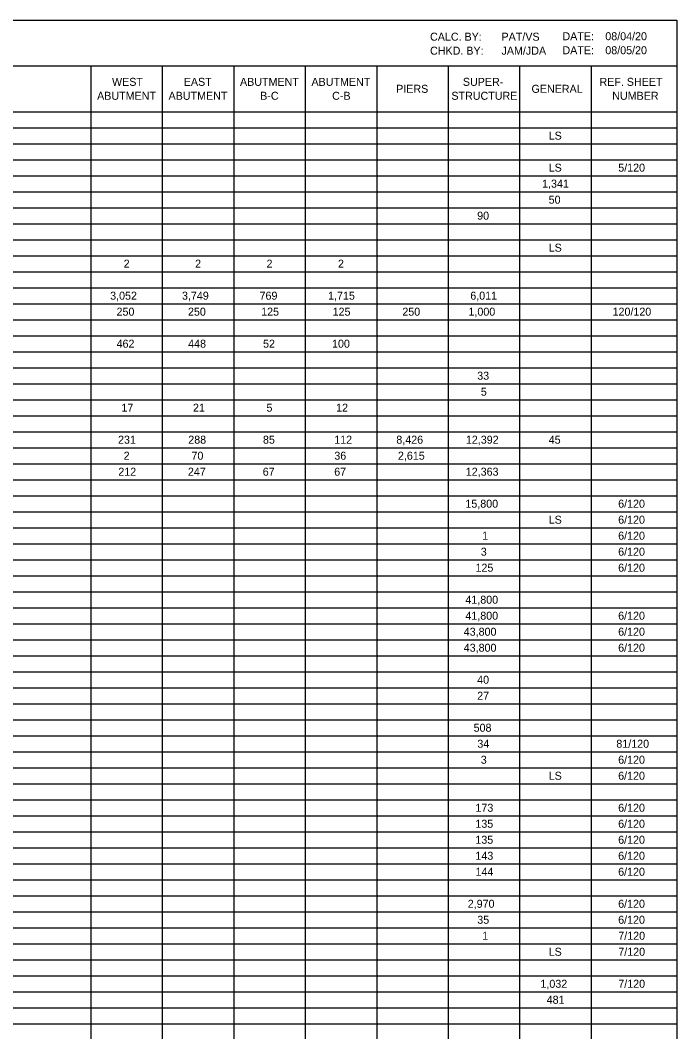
# Model space of a CAD drawing. Extents: x 100 to 128, y 64.8 to 100.
# Drawn here: x 116.51 to 128, y 82.3 to 100 of the extents above; entities that cross this region are included whole.
import ezdxf

# ---------------------------------------------------------------- set-up
doc = ezdxf.new("R2010")
doc.units = 0
doc.layers.add('SH_Text', color=7, linetype='Continuous')

msp = doc.modelspace()

# ---------------------------------------------------------------- linework, layer by layer
at = {"layer": 'SH_Text'}
for p, q in [((100, 100), (128, 100)), ((128, 100), (128, 98.4)), ((100, 99.2), (128, 99.2)), ((117.75, 99.2), (117.75, 98.4)), ((119, 99.2), (119, 98.4)), ((120.25, 99.2), (120.25, 98.4)), ((121.5, 99.2), (121.5, 98.4)), ((122.75, 99.2), (122.75, 98.4)), ((124, 99.2), (124, 98.4)), ((125.25, 99.2), (125.25, 98.4)), ((126.5, 99.2), (126.5, 98.4)), ((100, 98.4), (128, 98.4)), ((100, 98.4), (128, 98.4)), ((117.75, 98.4), (117.75, 95.32)), ((119, 98.4), (119, 95.32)), ((120.25, 98.4), (120.25, 95.32)), ((121.5, 98.4), (121.5, 95.32)), ((122.75, 98.4), (122.75, 95.32)), ((124, 98.4), (124, 95.32)), ((125.25, 98.4), (125.25, 95.32)), ((126.5, 98.4), (126.5, 95.32)), ((128, 98.4), (128, 95.32)), ((100, 98.12), (128, 98.12)), ((100, 97.84), (128, 97.84)), ((100, 97.56), (128, 97.56)), ((100, 97.28), (128, 97.28)), ((100, 97), (128, 97)), ((100, 96.72), (128, 96.72)), ((100, 96.44), (128, 96.44)), ((100, 96.16), (128, 96.16)), ((100, 95.88), (128, 95.88)), ((100, 95.6), (128, 95.6)), ((100, 95.32), (128, 95.32)), ((117.75, 95.32), (117.75, 92.24)), ((119, 95.32), (119, 92.24)), ((120.25, 95.32), (120.25, 92.24)), ((121.5, 95.32), (121.5, 92.24)), ((122.75, 95.32), (122.75, 92.24)), ((124, 95.32), (124, 92.24)), ((125.25, 95.32), (125.25, 92.24)), ((126.5, 95.32), (126.5, 92.24)), ((128, 95.32), (128, 92.24)), ((100, 95.04), (128, 95.04)), ((100, 94.76), (128, 94.76)), ((100, 94.48), (128, 94.48)), ((100, 94.2), (128, 94.2)), ((100, 93.92), (128, 93.92)), ((100, 93.64), (128, 93.64)), ((100, 93.36), (128, 93.36)), ((100, 93.08), (128, 93.08)), ((100, 92.8), (128, 92.8)), ((100, 92.52), (128, 92.52)), ((100, 92.24), (128, 92.24)), ((117.75, 92.24), (117.75, 91.96)), ((119, 92.24), (119, 91.96)), ((120.25, 92.24), (120.25, 91.96)), ((121.5, 92.24), (121.5, 91.96)), ((122.75, 92.24), (122.75, 91.96)), ((124, 92.24), (124, 91.96)), ((125.25, 92.24), (125.25, 91.96)), ((126.5, 92.24), (126.5, 91.96)), ((128, 92.24), (128, 91.96)), ((100, 91.96), (128, 91.96)), ((117.75, 91.96), (117.75, 91.68)), ((119, 91.96), (119, 91.68)), ((120.25, 91.96), (120.25, 91.68)), ((121.5, 91.96), (121.5, 91.68)), ((122.75, 91.96), (122.75, 91.68)), ((124, 91.96), (124, 91.68)), ((125.25, 91.96), (125.25, 91.68)), ((126.5, 91.96), (126.5, 91.68)), ((128, 91.96), (128, 91.68)), ((100, 91.68), (128, 91.68)), ((117.75, 91.68), (117.75, 91.4)), ((119, 91.68), (119, 91.4)), ((120.25, 91.68), (120.25, 91.4)), ((121.5, 91.68), (121.5, 91.4)), ((122.75, 91.68), (122.75, 91.4)), ((124, 91.68), (124, 91.4)), ((125.25, 91.68), (125.25, 91.4)), ((126.5, 91.68), (126.5, 91.4)), ((128, 91.68), (128, 91.4)), ((100, 91.4), (128, 91.4)), ((117.75, 91.4), (117.75, 91.12)), ((119, 91.4), (119, 91.12)), ((120.25, 91.4), (120.25, 91.12)), ((121.5, 91.4), (121.5, 91.12)), ((122.75, 91.4), (122.75, 91.12)), ((124, 91.4), (124, 91.12)), ((125.25, 91.4), (125.25, 91.12)), ((126.5, 91.4), (126.5, 91.12)), ((128, 91.4), (128, 91.12)), ((100, 91.12), (128, 91.12)), ((117.75, 91.12), (117.75, 90.84)), ((119, 91.12), (119, 90.84)), ((120.25, 91.12), (120.25, 90.84)), ((121.5, 91.12), (121.5, 90.84)), ((122.75, 91.12), (122.75, 90.84)), ((124, 91.12), (124, 90.84)), ((125.25, 91.12), (125.25, 90.84)), ((126.5, 91.12), (126.5, 90.84)), ((128, 91.12), (128, 90.84)), ((100, 90.84), (128, 90.84)), ((117.75, 90.84), (117.75, 90.56)), ((119, 90.84), (119, 90.56)), ((120.25, 90.84), (120.25, 90.56)), ((121.5, 90.84), (121.5, 90.56)), ((122.75, 90.84), (122.75, 90.56)), ((124, 90.84), (124, 90.56)), ((125.25, 90.84), (125.25, 90.56)), ((126.5, 90.84), (126.5, 90.56)), ((128, 90.84), (128, 90.56)), ((100, 90.56), (128, 90.56)), ((117.75, 90.56), (117.75, 90.28)), ((119, 90.56), (119, 90.28)), ((120.25, 90.56), (120.25, 90.28)), ((121.5, 90.56), (121.5, 90.28)), ((122.75, 90.56), (122.75, 90.28)), ((124, 90.56), (124, 90.28)), ((125.25, 90.56), (125.25, 90.28)), ((126.5, 90.56), (126.5, 90.28)), ((128, 90.56), (128, 90.28)), ((100, 90.28), (128, 90.28)), ((117.75, 90.28), (117.75, 90)), ((119, 90.28), (119, 90)), ((120.25, 90.28), (120.25, 90)), ((121.5, 90.28), (121.5, 90)), ((122.75, 90.28), (122.75, 90)), ((124, 90.28), (124, 90)), ((125.25, 90.28), (125.25, 90)), ((126.5, 90.28), (126.5, 90)), ((128, 90.28), (128, 90)), ((100, 90), (128, 90)), ((117.75, 90), (117.75, 89.72)), ((119, 90), (119, 89.72)), ((120.25, 90), (120.25, 89.72)), ((121.5, 90), (121.5, 89.72)), ((122.75, 90), (122.75, 89.72)), ((124, 90), (124, 89.72)), ((125.25, 90), (125.25, 89.72)), ((126.5, 90), (126.5, 89.72)), ((128, 90), (128, 89.72)), ((100, 89.72), (128, 89.72)), ((117.75, 89.72), (117.75, 89.44)), ((119, 89.72), (119, 89.44)), ((120.25, 89.72), (120.25, 89.44)), ((121.5, 89.72), (121.5, 89.44)), ((122.75, 89.72), (122.75, 89.44)), ((124, 89.72), (124, 89.44)), ((125.25, 89.72), (125.25, 89.44)), ((126.5, 89.72), (126.5, 89.44)), ((128, 89.72), (128, 89.44)), ((100, 89.44), (128, 89.44)), ((117.75, 89.44), (117.75, 89.16)), ((119, 89.44), (119, 89.16)), ((120.25, 89.44), (120.25, 89.16)), ((121.5, 89.44), (121.5, 89.16)), ((122.75, 89.44), (122.75, 89.16)), ((124, 89.44), (124, 89.16)), ((125.25, 89.44), (125.25, 89.16)), ((126.5, 89.44), (126.5, 89.16)), ((128, 89.44), (128, 89.16)), ((100, 89.16), (128, 89.16)), ((117.75, 89.16), (117.75, 88.88)), ((119, 89.16), (119, 88.88)), ((120.25, 89.16), (120.25, 88.88)), ((121.5, 89.16), (121.5, 88.88)), ((122.75, 89.16), (122.75, 88.88)), ((124, 89.16), (124, 88.88)), ((125.25, 89.16), (125.25, 88.88)), ((126.5, 89.16), (126.5, 88.88)), ((128, 89.16), (128, 88.88)), ((100, 88.88), (128, 88.88)), ((117.75, 88.88), (117.75, 88.6)), ((119, 88.88), (119, 88.6)), ((120.25, 88.88), (120.25, 88.6)), ((121.5, 88.88), (121.5, 88.6)), ((122.75, 88.88), (122.75, 88.6)), ((124, 88.88), (124, 88.6)), ((125.25, 88.88), (125.25, 88.6)), ((126.5, 88.88), (126.5, 88.6)), ((128, 88.88), (128, 88.6)), ((100, 88.6), (128, 88.6)), ((117.75, 88.6), (117.75, 88.32)), ((119, 88.6), (119, 88.32)), ((120.25, 88.6), (120.25, 88.32)), ((121.5, 88.6), (121.5, 88.32)), ((122.75, 88.6), (122.75, 88.32)), ((124, 88.6), (124, 88.32)), ((125.25, 88.6), (125.25, 88.32)), ((126.5, 88.6), (126.5, 88.32)), ((128, 88.6), (128, 88.32)), ((100, 88.32), (128, 88.32)), ((117.75, 88.32), (117.75, 88.04)), ((119, 88.32), (119, 88.04)), ((120.25, 88.32), (120.25, 88.04)), ((121.5, 88.32), (121.5, 88.04)), ((122.75, 88.32), (122.75, 88.04)), ((124, 88.32), (124, 88.04)), ((125.25, 88.32), (125.25, 88.04)), ((126.5, 88.32), (126.5, 88.04)), ((128, 88.32), (128, 88.04)), ((100, 88.04), (128, 88.04)), ((117.75, 88.04), (117.75, 87.76)), ((119, 88.04), (119, 87.76)), ((120.25, 88.04), (120.25, 87.76)), ((121.5, 88.04), (121.5, 87.76)), ((122.75, 88.04), (122.75, 87.76)), ((124, 88.04), (124, 87.76)), ((125.25, 88.04), (125.25, 87.76)), ((126.5, 88.04), (126.5, 87.76)), ((128, 88.04), (128, 87.76)), ((100, 87.76), (128, 87.76)), ((117.75, 87.76), (117.75, 87.48)), ((119, 87.76), (119, 87.48)), ((120.25, 87.76), (120.25, 87.48)), ((121.5, 87.76), (121.5, 87.48)), ((122.75, 87.76), (122.75, 87.48)), ((124, 87.76), (124, 87.48)), ((125.25, 87.76), (125.25, 87.48)), ((126.5, 87.76), (126.5, 87.48)), ((128, 87.76), (128, 87.48)), ((100, 87.48), (128, 87.48)), ((117.75, 87.48), (117.75, 87.2)), ((119, 87.48), (119, 87.2)), ((120.25, 87.48), (120.25, 87.2)), ((121.5, 87.48), (121.5, 87.2)), ((122.75, 87.48), (122.75, 87.2)), ((124, 87.48), (124, 87.2)), ((125.25, 87.48), (125.25, 87.2)), ((126.5, 87.48), (126.5, 87.2)), ((128, 87.48), (128, 87.2)), ((100, 87.2), (128, 87.2)), ((117.75, 87.2), (117.75, 86.92)), ((119, 87.2), (119, 86.92)), ((120.25, 87.2), (120.25, 86.92)), ((121.5, 87.2), (121.5, 86.92)), ((122.75, 87.2), (122.75, 86.92)), ((124, 87.2), (124, 86.92)), ((125.25, 87.2), (125.25, 86.92)), ((126.5, 87.2), (126.5, 86.92)), ((128, 87.2), (128, 86.92)), ((100, 86.92), (128, 86.92)), ((117.75, 86.92), (117.75, 86.64)), ((119, 86.92), (119, 86.64)), ((120.25, 86.92), (120.25, 86.64)), ((121.5, 86.92), (121.5, 86.64)), ((122.75, 86.92), (122.75, 86.64)), ((124, 86.92), (124, 86.64)), ((125.25, 86.92), (125.25, 86.64)), ((126.5, 86.92), (126.5, 86.64)), ((128, 86.92), (128, 86.64)), ((100, 86.64), (128, 86.64)), ((117.75, 86.64), (117.75, 86.36)), ((119, 86.64), (119, 86.36)), ((120.25, 86.64), (120.25, 86.36)), ((121.5, 86.64), (121.5, 86.36)), ((122.75, 86.64), (122.75, 86.36)), ((124, 86.64), (124, 86.36)), ((125.25, 86.64), (125.25, 86.36)), ((126.5, 86.64), (126.5, 86.36)), ((128, 86.64), (128, 86.36)), ((100, 86.36), (128, 86.36)), ((117.75, 86.36), (117.75, 86.08)), ((119, 86.36), (119, 86.08)), ((120.25, 86.36), (120.25, 86.08)), ((121.5, 86.36), (121.5, 86.08)), ((122.75, 86.36), (122.75, 86.08)), ((124, 86.36), (124, 86.08)), ((125.25, 86.36), (125.25, 86.08)), ((126.5, 86.36), (126.5, 86.08)), ((128, 86.36), (128, 86.08)), ((100, 86.08), (128, 86.08)), ((117.75, 86.08), (117.75, 85.8)), ((119, 86.08), (119, 85.8)), ((120.25, 86.08), (120.25, 85.8)), ((121.5, 86.08), (121.5, 85.8)), ((122.75, 86.08), (122.75, 85.8)), ((124, 86.08), (124, 85.8)), ((125.25, 86.08), (125.25, 85.8)), ((126.5, 86.08), (126.5, 85.8)), ((128, 86.08), (128, 85.8)), ((100, 85.8), (128, 85.8)), ((117.75, 85.8), (117.75, 85.52)), ((119, 85.8), (119, 85.52)), ((120.25, 85.8), (120.25, 85.52)), ((121.5, 85.8), (121.5, 85.52)), ((122.75, 85.8), (122.75, 85.52)), ((124, 85.8), (124, 85.52)), ((125.25, 85.8), (125.25, 85.52)), ((126.5, 85.8), (126.5, 85.52)), ((128, 85.8), (128, 85.52)), ((100, 85.52), (128, 85.52)), ((117.75, 85.52), (117.75, 85.24)), ((119, 85.52), (119, 85.24)), ((120.25, 85.52), (120.25, 85.24)), ((121.5, 85.52), (121.5, 85.24)), ((122.75, 85.52), (122.75, 85.24)), ((124, 85.52), (124, 85.24)), ((125.25, 85.52), (125.25, 85.24)), ((126.5, 85.52), (126.5, 85.24)), ((128, 85.52), (128, 85.24)), ((100, 85.24), (128, 85.24)), ((117.75, 85.24), (117.75, 84.96)), ((119, 85.24), (119, 84.96)), ((120.25, 85.24), (120.25, 84.96)), ((121.5, 85.24), (121.5, 84.96)), ((122.75, 85.24), (122.75, 84.96)), ((124, 85.24), (124, 84.96)), ((125.25, 85.24), (125.25, 84.96)), ((126.5, 85.24), (126.5, 84.96)), ((128, 85.24), (128, 84.96)), ((100, 84.96), (128, 84.96)), ((117.75, 84.96), (117.75, 84.68)), ((119, 84.96), (119, 84.68)), ((120.25, 84.96), (120.25, 84.68)), ((121.5, 84.96), (121.5, 84.68)), ((122.75, 84.96), (122.75, 84.68)), ((124, 84.96), (124, 84.68)), ((125.25, 84.96), (125.25, 84.68)), ((126.5, 84.96), (126.5, 84.68)), ((128, 84.96), (128, 84.68)), ((100, 84.68), (128, 84.68)), ((117.75, 84.68), (117.75, 84.4)), ((119, 84.68), (119, 84.4)), ((120.25, 84.68), (120.25, 84.4)), ((121.5, 84.68), (121.5, 84.4)), ((122.75, 84.68), (122.75, 84.4)), ((124, 84.68), (124, 84.4)), ((125.25, 84.68), (125.25, 84.4)), ((126.5, 84.68), (126.5, 84.4)), ((128, 84.68), (128, 84.4)), ((100, 84.4), (128, 84.4)), ((117.75, 84.4), (117.75, 84.12)), ((119, 84.4), (119, 84.12)), ((120.25, 84.4), (120.25, 84.12)), ((121.5, 84.4), (121.5, 84.12)), ((122.75, 84.4), (122.75, 84.12)), ((124, 84.4), (124, 84.12)), ((125.25, 84.4), (125.25, 84.12)), ((126.5, 84.4), (126.5, 84.12)), ((128, 84.4), (128, 84.12)), ((100, 84.12), (128, 84.12)), ((117.75, 84.12), (117.75, 83.84)), ((119, 84.12), (119, 83.84)), ((120.25, 84.12), (120.25, 83.84)), ((121.5, 84.12), (121.5, 83.84)), ((122.75, 84.12), (122.75, 83.84)), ((124, 84.12), (124, 83.84)), ((125.25, 84.12), (125.25, 83.84)), ((126.5, 84.12), (126.5, 83.84)), ((128, 84.12), (128, 83.84)), ((100, 83.84), (128, 83.84)), ((117.75, 83.84), (117.75, 83.56)), ((119, 83.84), (119, 83.56)), ((120.25, 83.84), (120.25, 83.56)), ((121.5, 83.84), (121.5, 83.56)), ((122.75, 83.84), (122.75, 83.56)), ((124, 83.84), (124, 83.56)), ((125.25, 83.84), (125.25, 83.56)), ((126.5, 83.84), (126.5, 83.56)), ((128, 83.84), (128, 83.56)), ((100, 83.56), (128, 83.56)), ((117.75, 83.56), (117.75, 83.28)), ((119, 83.56), (119, 83.28)), ((120.25, 83.56), (120.25, 83.28)), ((121.5, 83.56), (121.5, 83.28)), ((122.75, 83.56), (122.75, 83.28)), ((124, 83.56), (124, 83.28)), ((125.25, 83.56), (125.25, 83.28)), ((126.5, 83.56), (126.5, 83.28)), ((128, 83.56), (128, 83.28)), ((100, 83.28), (128, 83.28)), ((117.75, 83.28), (117.75, 83)), ((119, 83.28), (119, 83)), ((120.25, 83.28), (120.25, 83)), ((121.5, 83.28), (121.5, 83)), ((122.75, 83.28), (122.75, 83)), ((124, 83.28), (124, 83)), ((125.25, 83.28), (125.25, 83)), ((126.5, 83.28), (126.5, 83)), ((128, 83.28), (128, 83)), ((100, 83), (128, 83)), ((117.75, 83), (117.75, 82.72)), ((119, 83), (119, 82.72)), ((120.25, 83), (120.25, 82.72)), ((121.5, 83), (121.5, 82.72)), ((122.75, 83), (122.75, 82.72)), ((124, 83), (124, 82.72)), ((125.25, 83), (125.25, 82.72)), ((126.5, 83), (126.5, 82.72)), ((128, 83), (128, 82.72)), ((100, 82.72), (128, 82.72)), ((117.75, 82.72), (117.75, 82.44)), ((119, 82.72), (119, 82.44)), ((120.25, 82.72), (120.25, 82.44)), ((121.5, 82.72), (121.5, 82.44)), ((122.75, 82.72), (122.75, 82.44)), ((124, 82.72), (124, 82.44)), ((125.25, 82.72), (125.25, 82.44)), ((126.5, 82.72), (126.5, 82.44)), ((128, 82.72), (128, 82.44)), ((100, 82.44), (128, 82.44)), ((117.75, 82.44), (117.75, 82.16)), ((119, 82.44), (119, 82.16)), ((120.25, 82.44), (120.25, 82.16)), ((121.5, 82.44), (121.5, 82.16)), ((122.75, 82.44), (122.75, 82.16)), ((124, 82.44), (124, 82.16)), ((125.25, 82.44), (125.25, 82.16)), ((126.5, 82.44), (126.5, 82.16)), ((128, 82.44), (128, 82.16))]:
    msp.add_line(p, q, dxfattribs=at)

# ---------------------------------------------------------------- texts
for s, p in [('CALC. BY:', (123.684, 99.642)), ('PAT/VS', (124.934, 99.642)), ('DATE:', (126, 99.65)), ('08/04/20', (126.75, 99.65)), ('CHKD. BY:', (123.684, 99.397)), ('JAM/JDA', (124.934, 99.397)), ('DATE:', (126, 99.405)), ('08/05/20', (126.75, 99.405)), ('WEST', (118.12, 98.852)), ('EAST', (119.375, 98.852)), ('ABUTMENT', (120.359, 98.852)), ('ABUTMENT', (121.609, 98.852)), ('SUPER-', (124.258, 98.852)), ('REF. SHEET', (126.648, 98.852)), ('PIERS', (123.091, 98.73)), ('GENERAL', (125.459, 98.73)), ('ABUTMENT', (117.859, 98.608)), ('ABUTMENT', (119.109, 98.608)), ('B-C', (120.712, 98.608)), ('C-B', (121.971, 98.608)), ('STRUCTURE', (124.057, 98.608)), ('NUMBER', (126.871, 98.608)), ('LS', (125.759, 97.91)), ('LS', (125.759, 97.35)), ('5/120', (126.976, 97.35)), ('1,341', (125.644, 97.07)), ('50', (125.759, 96.79)), ('90', (124.508, 96.51)), ('LS', (125.759, 95.95)), ('2', (118.323, 95.67)), ('2', (119.573, 95.67)), ('2', (120.823, 95.67)), ('2', (122.073, 95.67)), ('3,052', (118.087, 95.11)), ('3,749', (119.344, 95.11)), ('769', (120.701, 95.11)), ('1,715', (121.9, 95.11)), ('6,011', (124.388, 95.11)), ('250', (118.199, 94.83)), ('250', (119.449, 94.83)), ('125', (120.729, 94.83)), ('125', (121.979, 94.83)), ('250', (123.199, 94.83)), ('1,000', (124.356, 94.83)), ('120/120', (126.877, 94.83)), ('462', (118.2, 94.27)), ('448', (119.452, 94.27)), ('52', (120.762, 94.27)), ('100', (121.969, 94.27)), ('33', (124.509, 93.71)), ('5', (124.572, 93.43)), ('17', (118.285, 93.15)), ('21', (119.536, 93.15)), ('5', (120.822, 93.15)), ('12', (122.04, 93.15)), ('231', (118.225, 92.59)), ('288', (119.454, 92.59)), ('85', (120.761, 92.59)), ('112', (122.007, 92.59)), ('8,426', (123.094, 92.59)), ('12,392', (124.311, 92.59)), ('45', (125.76, 92.59)), ('2', (118.323, 92.31)), ('70', (119.51, 92.31)), ('36', (122.009, 92.31)), ('2,615', (123.122, 92.31)), ('212', (118.23, 92.03)), ('247', (119.448, 92.03)), ('67', (120.757, 92.03)), ('67', (122.007, 92.03)), ('12,363', (124.309, 92.03)), ('15,800', (124.302, 91.47)), ('6/120', (126.975, 91.47)), ('LS', (125.759, 91.19)), ('6/120', (126.975, 91.19)), ('1', (124.596, 90.91)), ('6/120', (126.975, 90.91)), ('3', (124.571, 90.63)), ('6/120', (126.975, 90.63)), ('125', (124.479, 90.35)), ('6/120', (126.975, 90.35)), ('41,800', (124.302, 89.79)), ('41,800', (124.302, 89.51)), ('6/120', (126.975, 89.51)), ('43,800', (124.273, 89.23)), ('6/120', (126.975, 89.23)), ('43,800', (124.273, 88.95)), ('6/120', (126.975, 88.95)), ('40', (124.508, 88.39)), ('27', (124.509, 88.11)), ('508', (124.446, 87.55)), ('34', (124.511, 87.27)), ('81/120', (126.943, 87.27)), ('3', (124.571, 86.99)), ('6/120', (126.975, 86.99)), ('LS', (125.759, 86.71)), ('6/120', (126.975, 86.71)), ('173', (124.478, 86.15)), ('6/120', (126.975, 86.15)), ('135', (124.477, 85.87)), ('6/120', (126.975, 85.87)), ('135', (124.477, 85.59)), ('6/120', (126.975, 85.59)), ('143', (124.477, 85.31)), ('6/120', (126.975, 85.31)), ('144', (124.479, 85.03)), ('6/120', (126.975, 85.03)), ('2,970', (124.343, 84.47)), ('6/120', (126.975, 84.47)), ('35', (124.51, 84.19)), ('6/120', (126.975, 84.19)), ('1', (124.596, 83.91)), ('7/120', (126.977, 83.91)), ('LS', (125.759, 83.63)), ('7/120', (126.977, 83.63)), ('1,032', (125.615, 83.07)), ('7/120', (126.977, 83.07)), ('481', (125.724, 82.79))]:
    msp.add_text(s, height=0.14, dxfattribs=at).set_placement(p)

doc.saveas('drawing.dxf')
